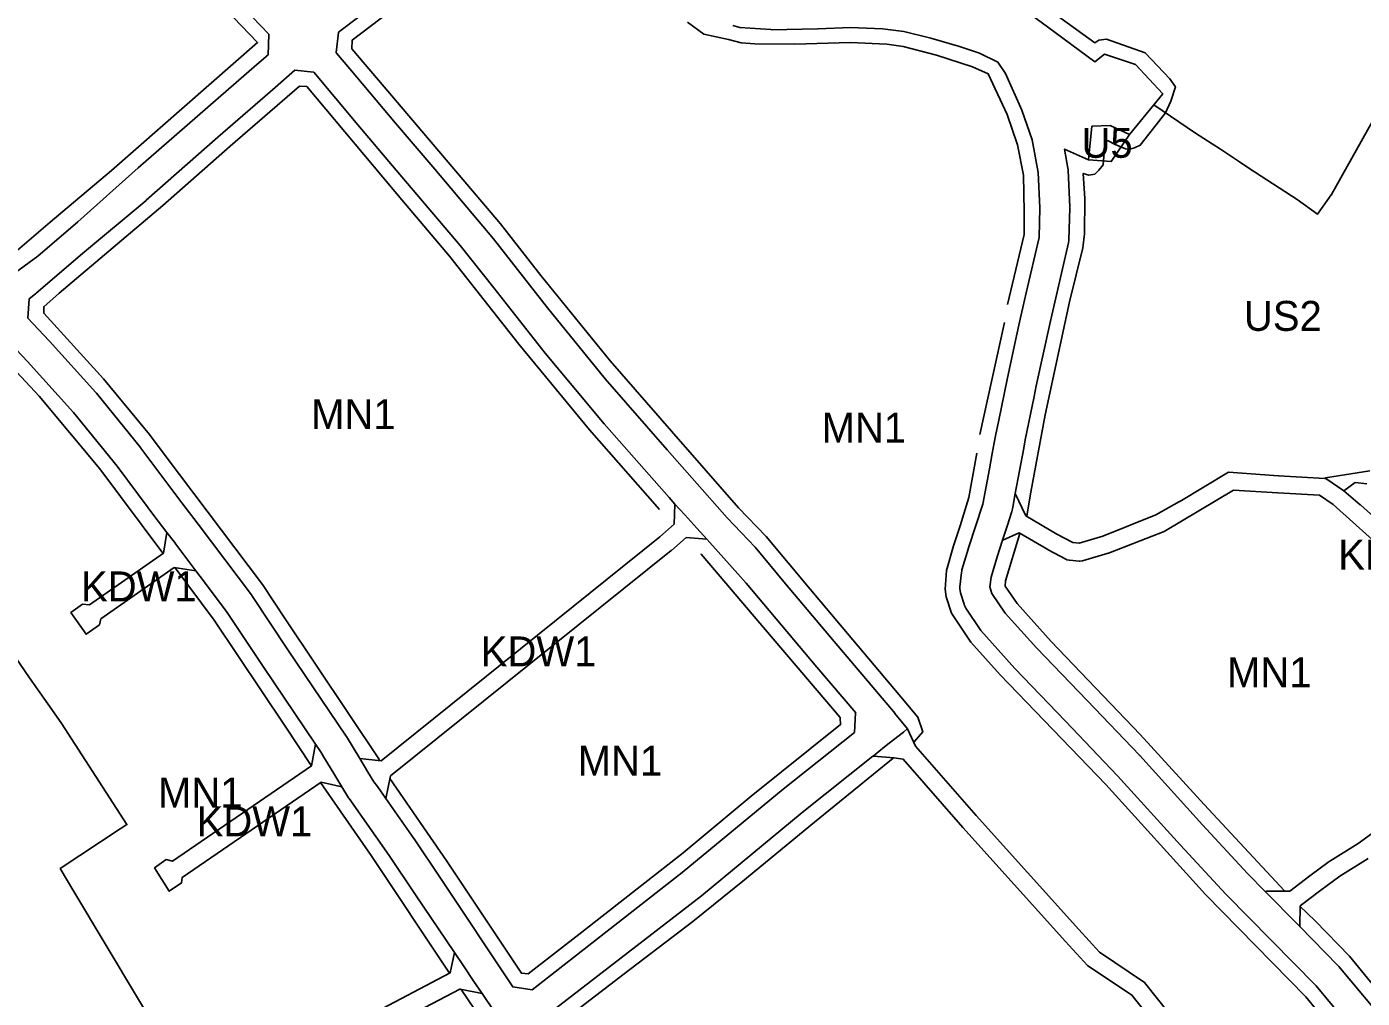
# Model space of a CAD drawing. Extents: x -284239 to -281592, y 34477 to 37267.
# Drawn here: x -283958.8 to -283512.6, y 34964.3 to 35288.9 of the extents above; entities that cross this region are included whole.
import ezdxf

# ---------------------------------------------------------------- set-up
doc = ezdxf.new("R2010")
doc.units = 0
for name, color, linetype in [('linie_rozgraniczajace', 7, 'Continuous'), ('linie_zabudowy_nieprzekraczalne', 7, 'Continuous'), ('oznaczenia_przeznaczen', 7, 'Continuous')]:
    doc.layers.add(name, color=color, linetype=linetype)

msp = doc.modelspace()

# ---------------------------------------------------------------- linework, layer by layer
at = {"layer": 'linie_rozgraniczajace'}
for points in [[(-283967.091, 35203.375), (-283955.019, 35212.204), (-283941.685, 35223.735), (-283921.504, 35241.754), (-283881.863, 35276.26), (-283878.079, 35279.504), (-283877.899, 35286.351), (-283897.359, 35306.712)], [(-283897.359, 35306.712), (-283877.899, 35286.351), (-283878.079, 35279.504), (-283881.863, 35276.26), (-283921.504, 35241.754), (-283941.685, 35223.735), (-283955.019, 35212.204), (-283967.091, 35203.375)], [(-283460.618, 35234.062), (-283475.613, 35245.965), (-283496.173, 35262.042), (-283502.975, 35267.607), (-283509.313, 35257.095), (-283522.917, 35232.825), (-283522.917, 35232.636), (-283523.014, 35232.725), (-283527.552, 35226.283), (-283534.386, 35231.101), (-283550.521, 35241.633), (-283553.587, 35243.683), (-283559.988, 35247.963), (-283568.279, 35253.341), (-283582.285, 35262.753), (-283579.201, 35266.417), (-283588.366, 35276.203), (-283598.698, 35279.683), (-283601.902, 35277.142), (-283617.703, 35288.854), (-283630.702, 35298.362), (-283632.444, 35304.207)], [(-283630.702, 35298.362), (-283617.703, 35288.854), (-283601.902, 35277.142), (-283598.698, 35279.683), (-283588.366, 35276.203), (-283579.201, 35266.417), (-283582.285, 35262.753), (-283590.352, 35252.893), (-283596.794, 35255.862), (-283602.913, 35255.619), (-283604.057, 35244.38), (-283612.117, 35247.946), (-283610.945, 35241.662), (-283610.891, 35241.076), (-283610.865, 35240.958), (-283610.339, 35228.584), (-283610.368, 35228.419), (-283610.336, 35228.247), (-283610.599, 35217.716), (-283610.626, 35217.587), (-283610.725, 35216.718), (-283616.314, 35192.455), (-283616.853, 35190.004), (-283621.5, 35168.889), (-283622.227, 35165.304), (-283625.17, 35150.802), (-283625.688, 35148.026), (-283628.518, 35132.864), (-283629.36, 35128.347), (-283629.705, 35126.763), (-283629.736, 35126.572), (-283631.126, 35122.327), (-283632.758, 35117.341), (-283634.585, 35111.762), (-283636.61, 35104.951), (-283636.972, 35101.693), (-283636.311, 35099.563), (-283631.912, 35092.964), (-283621.416, 35081.316), (-283604.552, 35063.795), (-283587.039, 35045.493), (-283586.996, 35045.426), (-283586.942, 35045.388), (-283565.967, 35022.178), (-283550.9, 35005.932), (-283545.059, 34999.989), (-283541.589, 34996.458), (-283537.347, 34992.143), (-283533.503, 34988.231), (-283520.736, 34975.24), (-283520.466, 34974.943), (-283507.888, 34959.86)], [(-283847.419, 35292.551), (-283854.627, 35287.038), (-283854.63, 35286.972), (-283855.381, 35280.213), (-283855.332, 35280.025), (-283850.849, 35274.762), (-283835.547, 35256.605), (-283822.414, 35241.303), (-283802.83, 35217.95), (-283784.844, 35194.939), (-283765.487, 35171.243), (-283744.761, 35147.547), (-283724.719, 35124.765), (-283715.412, 35115.002)], [(-283855.381, 35280.213), (-283854.63, 35286.972), (-283854.627, 35287.038), (-283847.419, 35292.551)], [(-283515.605, 34953.503), (-283528.014, 34968.381), (-283558.083, 34998.974), (-283558.183, 34999.078), (-283573.321, 35015.401), (-283594.314, 35038.631), (-283611.767, 35056.872), (-283628.678, 35074.44), (-283640.03, 35087.114), (-283645.032, 35094.617), (-283645.492, 35095.477), (-283645.647, 35095.909), (-283646.832, 35099.726), (-283647.057, 35101.208), (-283647.026, 35101.76), (-283646.5, 35106.499), (-283646.385, 35106.945), (-283646.323, 35107.372), (-283644.151, 35114.678), (-283644.11, 35114.809), (-283639.342, 35129.37), (-283637.136, 35141.192), (-283636.193, 35146.243), (-283635.518, 35149.861), (-283635.083, 35152.192), (-283634.031, 35157.385), (-283631.275, 35170.998), (-283628.396, 35184.082), (-283627.285, 35189.13), (-283626.62, 35192.153), (-283625.964, 35195.055), (-283624.833, 35199.979), (-283620.583, 35218.471), (-283620.337, 35228.328), (-283620.841, 35240.179), (-283622.876, 35251.095), (-283626.37, 35260.953), (-283631.776, 35273.273), (-283634.323, 35277.046), (-283640.479, 35280.018), (-283647.104, 35282.308), (-283656.773, 35285.016), (-283665.748, 35287.292), (-283672.885, 35288.153), (-283683.523, 35288.659), (-283694.343, 35288.144), (-283694.496, 35288.139), (-283710.03, 35287.876), (-283710.232, 35287.914), (-283720.495, 35288.596), (-283722.896, 35289.305)], [(-283722.896, 35289.305), (-283720.495, 35288.596), (-283710.232, 35287.914), (-283710.03, 35287.876), (-283694.496, 35288.139), (-283694.343, 35288.144), (-283683.523, 35288.659), (-283672.885, 35288.153), (-283665.748, 35287.292), (-283656.773, 35285.016), (-283647.104, 35282.308), (-283640.479, 35280.018), (-283634.323, 35277.046), (-283631.776, 35273.273), (-283626.37, 35260.953), (-283622.876, 35251.095), (-283620.841, 35240.179), (-283620.337, 35228.328), (-283620.583, 35218.471), (-283624.833, 35199.979), (-283625.964, 35195.055), (-283626.62, 35192.153), (-283627.285, 35189.13), (-283628.396, 35184.082), (-283631.275, 35170.998), (-283634.031, 35157.385), (-283635.083, 35152.192), (-283635.518, 35149.861), (-283636.193, 35146.243), (-283637.136, 35141.192), (-283639.342, 35129.37), (-283644.11, 35114.809), (-283644.151, 35114.678), (-283646.323, 35107.372), (-283646.385, 35106.945), (-283646.5, 35106.499), (-283647.026, 35101.76), (-283647.057, 35101.208), (-283646.832, 35099.726), (-283645.647, 35095.909), (-283645.492, 35095.477), (-283645.032, 35094.617), (-283640.03, 35087.114), (-283628.678, 35074.44), (-283611.767, 35056.872), (-283594.314, 35038.631), (-283573.321, 35015.401), (-283558.183, 34999.078), (-283558.083, 34998.974), (-283528.014, 34968.381), (-283515.605, 34953.503)], [(-283664.54, 35054.239), (-283664.589, 35054.271), (-283664.54, 35054.31), (-283668.767, 35059.383), (-283668.696, 35059.435), (-283688.976, 35083.426), (-283705.249, 35102.782), (-283715.412, 35115.002), (-283724.719, 35124.765), (-283744.761, 35147.547), (-283765.487, 35171.243), (-283784.844, 35194.939), (-283802.83, 35217.95), (-283822.414, 35241.303), (-283835.547, 35256.605), (-283850.849, 35274.762), (-283855.332, 35280.025), (-283855.381, 35280.213)], [(-283510.06, 35140.514), (-283524.877, 35138.133), (-283525.103, 35137.954), (-283540.523, 35138.846), (-283540.558, 35138.848), (-283545.143, 35139.113), (-283557.275, 35140.041), (-283573.548, 35130.294), (-283573.608, 35130.267), (-283573.684, 35130.232), (-283581.569, 35125.767), (-283599.272, 35118.677), (-283607.221, 35116.353), (-283609.339, 35116.523), (-283614.65, 35119.355), (-283624.971, 35125.499), (-283628.518, 35132.864), (-283625.688, 35148.026), (-283625.17, 35150.802), (-283622.227, 35165.304), (-283621.5, 35168.889), (-283616.853, 35190.004), (-283616.314, 35192.455), (-283610.725, 35216.718), (-283610.626, 35217.587), (-283610.599, 35217.716), (-283610.336, 35228.247), (-283610.368, 35228.419), (-283610.339, 35228.584), (-283610.865, 35240.958), (-283610.891, 35241.076), (-283610.945, 35241.662), (-283612.117, 35247.946), (-283604.057, 35244.38), (-283596.432, 35243.828), (-283590.352, 35252.893), (-283582.285, 35262.753), (-283568.279, 35253.341), (-283559.988, 35247.963), (-283553.587, 35243.683), (-283550.521, 35241.633), (-283534.386, 35231.101), (-283527.552, 35226.283), (-283523.014, 35232.725), (-283522.917, 35232.636), (-283522.917, 35232.825), (-283509.313, 35257.095)], [(-283782.296, 34929.748), (-283806.652, 34965.834), (-283809.348, 34969.828), (-283812.902, 34975.093), (-283815.901, 34979.537), (-283828.92, 34998.827), (-283837.64, 35011.988), (-283851.063, 35031.012), (-283851.15, 35031.168), (-283851.249, 35031.295), (-283853.451, 35034.911), (-283856.188, 35039.409), (-283859.469, 35044.8), (-283860.442, 35046.398), (-283862.32, 35049.187), (-283879.803, 35075.152), (-283891.789, 35093.211), (-283899.75, 35103.764), (-283902.28, 35107.118), (-283905.31, 35111.135), (-283908.957, 35115.969), (-283909.447, 35116.618), (-283911.957, 35119.889), (-283914.892, 35123.716), (-283914.924, 35123.757), (-283928.581, 35142.02), (-283943.14, 35160.014), (-283958.538, 35177.051), (-283965.895, 35184.8)], [(-283965.895, 35184.8), (-283958.538, 35177.051), (-283943.14, 35160.014), (-283928.581, 35142.02), (-283914.924, 35123.757), (-283914.892, 35123.716), (-283911.957, 35119.889), (-283913.126, 35113.031), (-283937.76, 35095.667), (-283940.141, 35095.932), (-283943.978, 35093.154), (-283938.951, 35085.877), (-283934.453, 35089.052), (-283934.056, 35091.037), (-283909.48, 35108.219), (-283902.28, 35107.118), (-283899.75, 35103.764), (-283891.789, 35093.211), (-283879.803, 35075.152), (-283862.32, 35049.187), (-283863.657, 35041.928), (-283910.111, 35010.074), (-283912.228, 35010.603), (-283916.064, 35007.825), (-283911.169, 35000.02), (-283907.068, 35002.798), (-283906.804, 35004.65), (-283860.408, 35036.511), (-283853.451, 35034.911), (-283851.249, 35031.295), (-283851.15, 35031.168), (-283851.063, 35031.012), (-283837.64, 35011.988), (-283828.92, 34998.827), (-283815.901, 34979.537), (-283817.35, 34972.75), (-283870.556, 34944.722)], [(-283503.756, 35112.492), (-283522.352, 35129.294), (-283526.942, 35132.354), (-283540.811, 35133.133), (-283555.628, 35134.002), (-283578.824, 35120.277), (-283597.369, 35112.988), (-283597.511, 35112.94), (-283606.067, 35110.439), (-283606.909, 35110.319), (-283607.148, 35110.328), (-283610.439, 35110.592), (-283611.348, 35110.81), (-283611.612, 35110.935), (-283617.536, 35114.094), (-283617.568, 35114.118), (-283617.658, 35114.164), (-283627.17, 35119.825), (-283632.708, 35117.32), (-283632.758, 35117.341), (-283631.126, 35122.327), (-283629.736, 35126.572), (-283629.705, 35126.763), (-283629.36, 35128.347), (-283628.518, 35132.864), (-283624.971, 35125.499), (-283614.65, 35119.355), (-283609.339, 35116.523), (-283607.221, 35116.353), (-283599.272, 35118.677), (-283581.569, 35125.767), (-283573.684, 35130.232), (-283573.608, 35130.267), (-283573.548, 35130.294), (-283557.275, 35140.041), (-283545.143, 35139.113), (-283540.558, 35138.848), (-283540.523, 35138.846), (-283525.103, 35137.954), (-283524.807, 35137.937), (-283518.767, 35133.76), (-283513.271, 35129.175), (-283513.241, 35129.148), (-283513.192, 35129.104), (-283499.654, 35116.872)], [(-283511.119, 35136.148), (-283514.969, 35136.607), (-283518.767, 35133.76), (-283524.807, 35137.937), (-283525.103, 35137.954), (-283524.877, 35138.133), (-283510.06, 35140.514)], [(-283499.654, 35116.872), (-283513.192, 35129.104), (-283513.241, 35129.148), (-283513.271, 35129.175), (-283518.767, 35133.76), (-283514.969, 35136.607), (-283511.119, 35136.148)], [(-283500.658, 35025.661), (-283513.918, 35016.002), (-283523.409, 35010.111), (-283523.513, 35010.028), (-283523.617, 35009.969), (-283530.072, 35005.169), (-283536.83, 35000.057), (-283544.648, 35000.057), (-283545.059, 34999.989), (-283550.9, 35005.932), (-283565.967, 35022.178), (-283586.942, 35045.388), (-283586.996, 35045.426), (-283587.039, 35045.493), (-283604.552, 35063.795), (-283621.416, 35081.316), (-283631.912, 35092.964), (-283636.311, 35099.563), (-283636.972, 35101.693), (-283636.61, 35104.951), (-283634.585, 35111.762), (-283632.758, 35117.341), (-283632.708, 35117.32), (-283627.17, 35119.825), (-283617.658, 35114.164), (-283617.568, 35114.118), (-283617.536, 35114.094), (-283611.612, 35110.935), (-283611.348, 35110.81), (-283610.439, 35110.592), (-283607.148, 35110.328), (-283606.909, 35110.319), (-283606.067, 35110.439), (-283597.511, 35112.94), (-283597.369, 35112.988), (-283578.824, 35120.277), (-283555.628, 35134.002), (-283540.811, 35133.133), (-283526.942, 35132.354), (-283522.352, 35129.294), (-283503.756, 35112.492)], [(-283715.412, 35115.002), (-283705.249, 35102.782), (-283688.976, 35083.426), (-283668.696, 35059.435), (-283668.767, 35059.383), (-283664.54, 35054.31), (-283664.589, 35054.271), (-283665.909, 35053.22), (-283670.607, 35049.479), (-283672.157, 35048.244), (-283675.981, 35045.199), (-283676.085, 35045.213), (-283699.758, 35026.36), (-283733.394, 34998.539), (-283784.602, 34959.014)], [(-283962.68, 35078.32), (-283957.788, 35071.359), (-283951.668, 35062.652), (-283947.21, 35056.31), (-283925.27, 35022.31), (-283927.512, 35020.829), (-283947.54, 35007.6), (-283943, 35000), (-283911.001, 34946.396)], [(-283911.001, 34946.396), (-283943, 35000), (-283947.54, 35007.6), (-283927.512, 35020.829), (-283925.27, 35022.31), (-283947.21, 35056.31), (-283951.668, 35062.652), (-283957.788, 35071.359), (-283962.68, 35078.32)], [(-283580.307, 34953.784), (-283589.568, 34965.359), (-283604.367, 34975.171), (-283611.735, 34983.25), (-283646.006, 35021.357), (-283646.026, 35021.382), (-283665.933, 35044.135), (-283669.037, 35044.646), (-283668.984, 35044.585), (-283675.981, 35045.199), (-283672.157, 35048.244), (-283670.607, 35049.479), (-283665.909, 35053.22), (-283664.589, 35054.271), (-283664.54, 35054.239), (-283661.893, 35048.5), (-283641.531, 35025.353), (-283607.288, 34987.276), (-283600.406, 34979.732), (-283585.334, 34969.593), (-283552.394, 34928.119)], [(-283552.394, 34928.119), (-283585.334, 34969.593), (-283600.406, 34979.732), (-283607.288, 34987.276), (-283641.531, 35025.353), (-283661.893, 35048.5), (-283664.54, 35054.239)], [(-283784.602, 34959.014), (-283733.394, 34998.539), (-283699.758, 35026.36), (-283676.085, 35045.213), (-283675.981, 35045.199), (-283668.984, 35044.585), (-283669.037, 35044.646), (-283665.933, 35044.135), (-283646.026, 35021.382), (-283646.006, 35021.357), (-283611.735, 34983.25), (-283604.367, 34975.171), (-283589.568, 34965.359), (-283580.307, 34953.784)], [(-283510.66, 35010.962), (-283520.138, 35005.08), (-283526.471, 35000.37), (-283533.39, 34995.137), (-283533.503, 34988.231), (-283537.347, 34992.143), (-283541.589, 34996.458), (-283545.059, 34999.989), (-283544.648, 35000.057), (-283536.83, 35000.057), (-283530.072, 35005.169), (-283523.617, 35009.969), (-283523.513, 35010.028), (-283523.409, 35010.111), (-283513.918, 35016.002), (-283500.658, 35025.661)], [(-283507.888, 34959.86), (-283520.466, 34974.943), (-283520.736, 34975.24), (-283533.503, 34988.231), (-283533.39, 34995.137), (-283526.471, 35000.37), (-283520.138, 35005.08), (-283510.66, 35010.962)], [(-283867.645, 34939.298), (-283814.052, 34967.365), (-283813.935, 34967.344), (-283806.652, 34965.834), (-283782.296, 34929.748)]]:
    msp.add_lwpolyline(points, dxfattribs=at)
for points in [[(-283958.419, 35191.541), (-283951.244, 35183.891), (-283951.206, 35183.834), (-283951.16, 35183.802), (-283935.629, 35166.618), (-283935.607, 35166.583), (-283935.452, 35166.41), (-283920.747, 35148.236), (-283920.718, 35148.187), (-283920.629, 35148.085), (-283906.934, 35129.77), (-283901.497, 35122.684), (-283901.476, 35122.657), (-283883.714, 35099.113), (-283883.651, 35099.003), (-283883.54, 35098.866), (-283871.488, 35080.706), (-283852.083, 35051.888), (-283852.023, 35051.775), (-283851.96, 35051.695), (-283847.505, 35044.377), (-283844.875, 35040.056), (-283842.795, 35036.639), (-283841.633, 35034.992), (-283838.806, 35030.985), (-283829.427, 35017.694), (-283829.393, 35017.633), (-283829.344, 35017.573), (-283820.59, 35004.359), (-283796.401, 34968.072), (-283789.937, 34967.093), (-283789.907, 34967.075), (-283739.761, 35006.25), (-283706.086, 35034.101), (-283706.026, 35034.152), (-283682.25, 35053.075), (-283681.844, 35059.633), (-283681.786, 35059.652), (-283694.857, 35074.919), (-283718.438, 35102.954), (-283730.6, 35116.6), (-283731.577, 35117.654), (-283734.894, 35121.327), (-283738.929, 35125.769), (-283742.215, 35129.386), (-283744.19, 35131.56), (-283765.83, 35156.169), (-283785.529, 35179.751), (-283802.716, 35201.62), (-283813.964, 35215.723), (-283835.376, 35240.903), (-283848.109, 35256.034), (-283862.904, 35273.647), (-283862.984, 35273.642), (-283869.188, 35274.377), (-283875.737, 35268.568), (-283875.772, 35268.547), (-283875.79, 35268.523), (-283894.949, 35252.006), (-283918.815, 35230.919), (-283918.917, 35230.829), (-283940.181, 35213.131), (-283955.625, 35199.799), (-283955.669, 35199.772), (-283955.812, 35199.646), (-283957.932, 35197.997)], [(-283958.419, 35191.541), (-283957.932, 35197.997), (-283955.812, 35199.646), (-283955.669, 35199.772), (-283955.625, 35199.799), (-283940.181, 35213.131), (-283918.917, 35230.829), (-283918.815, 35230.919), (-283894.949, 35252.006), (-283875.79, 35268.523), (-283875.772, 35268.547), (-283875.737, 35268.568), (-283869.188, 35274.377), (-283862.984, 35273.642), (-283862.904, 35273.647), (-283848.109, 35256.034), (-283835.376, 35240.903), (-283813.964, 35215.723), (-283802.716, 35201.62), (-283785.529, 35179.751), (-283765.83, 35156.169), (-283744.19, 35131.56), (-283742.215, 35129.386), (-283742.244, 35129.378), (-283742.484, 35122.643), (-283747.241, 35118.461), (-283840.407, 35043.63), (-283847.505, 35044.377), (-283851.96, 35051.695), (-283852.023, 35051.775), (-283852.083, 35051.888), (-283871.488, 35080.706), (-283883.54, 35098.866), (-283883.651, 35099.003), (-283883.714, 35099.113), (-283901.476, 35122.657), (-283901.497, 35122.684), (-283906.934, 35129.77), (-283920.629, 35148.085), (-283920.718, 35148.187), (-283920.747, 35148.236), (-283935.452, 35166.41), (-283935.607, 35166.583), (-283935.629, 35166.618), (-283951.16, 35183.802), (-283951.206, 35183.834), (-283951.244, 35183.891)], [(-283604.057, 35244.38), (-283602.913, 35255.619), (-283596.794, 35255.862), (-283590.352, 35252.893), (-283596.432, 35243.828)], [(-283847.505, 35044.377), (-283840.407, 35043.63), (-283747.241, 35118.461), (-283742.484, 35122.643), (-283742.244, 35129.378), (-283742.215, 35129.386), (-283738.929, 35125.769), (-283734.894, 35121.327), (-283731.577, 35117.654), (-283738.459, 35118.193), (-283743.339, 35113.906), (-283743.428, 35113.828), (-283837.216, 35038.537), (-283838.806, 35030.985), (-283841.633, 35034.992), (-283842.795, 35036.639), (-283844.875, 35040.056)], [(-283943.978, 35093.154), (-283940.141, 35095.932), (-283937.76, 35095.667), (-283913.126, 35113.031), (-283911.957, 35119.889), (-283909.447, 35116.618), (-283908.957, 35115.969), (-283905.31, 35111.135), (-283902.28, 35107.118), (-283909.48, 35108.219), (-283934.056, 35091.037), (-283934.453, 35089.052), (-283938.951, 35085.877)], [(-283838.806, 35030.985), (-283837.216, 35038.537), (-283743.428, 35113.828), (-283743.339, 35113.906), (-283738.459, 35118.193), (-283731.577, 35117.654), (-283730.6, 35116.6), (-283718.438, 35102.954), (-283694.857, 35074.919), (-283681.786, 35059.652), (-283681.844, 35059.633), (-283682.25, 35053.075), (-283706.026, 35034.152), (-283706.086, 35034.101), (-283739.761, 35006.25), (-283789.907, 34967.075), (-283789.937, 34967.093), (-283796.401, 34968.072), (-283820.59, 35004.359), (-283829.344, 35017.573), (-283829.393, 35017.633), (-283829.427, 35017.694)], [(-283916.064, 35007.825), (-283912.228, 35010.603), (-283910.111, 35010.074), (-283863.657, 35041.928), (-283862.32, 35049.187), (-283860.442, 35046.398), (-283859.469, 35044.8), (-283856.188, 35039.409), (-283853.451, 35034.911), (-283860.408, 35036.511), (-283906.804, 35004.65), (-283907.068, 35002.798), (-283911.169, 35000.02)], [(-283876.244, 34943.267), (-283872.54, 34945.251), (-283870.556, 34944.722), (-283817.35, 34972.75), (-283815.901, 34979.537), (-283812.902, 34975.093), (-283809.348, 34969.828), (-283806.652, 34965.834), (-283813.935, 34967.344), (-283814.052, 34967.365), (-283867.645, 34939.298), (-283868.042, 34937.578), (-283871.879, 34935.726)]]:
    msp.add_lwpolyline(points, close=True, dxfattribs=at)
at = {"layer": 'linie_zabudowy_nieprzekraczalne'}
for points in [[(-283505.4, 35472.008), (-283529.874, 35442.44), (-283544.029, 35426.433), (-283573.398, 35394.352), (-283590.199, 35379.006), (-283593.374, 35375.435), (-283596.946, 35371.4), (-283602.767, 35361.478), (-283614.541, 35335.482), (-283627.505, 35308.759), (-283627.505, 35305.055), (-283626.447, 35301.351), (-283601.973, 35283.492), (-283600.65, 35284.418), (-283598.004, 35284.748), (-283585.172, 35280.118), (-283576.839, 35271.442), (-283574.995, 35268.777), (-283576.583, 35264.015), (-283578.302, 35260.046)], [(-283990.921, 35187.021), (-283984.165, 35194.724), (-283971.994, 35205.969), (-283966.57, 35210.202), (-283950.959, 35223.563), (-283930.454, 35240.828), (-283881.638, 35283.624), (-283935.094, 35339.421)], [(-283827.928, 35301.351), (-283850.02, 35284.418), (-283850.153, 35281.507), (-283831.103, 35259.084), (-283800.543, 35222.968), (-283787.05, 35205.704), (-283763.898, 35177.261), (-283743.393, 35153.779), (-283721.036, 35128.115), (-283711.775, 35118.59), (-283697.091, 35100.929), (-283666.796, 35064.945), (-283661.117, 35058.169), (-283659.397, 35053.274), (-283662.308, 35049.966)], [(-283724.353, 35284.652), (-283732.555, 35286.372), (-283737.979, 35290.341)], [(-283631.087, 35196.017), (-283625.521, 35219.396), (-283625.521, 35227.069), (-283625.786, 35239.306), (-283627.77, 35249.36), (-283631.21, 35259.547), (-283637.56, 35273.173), (-283642.851, 35275.488), (-283654.89, 35279.324), (-283666.002, 35282.235), (-283671.426, 35283.029), (-283683.597, 35283.558), (-283702.25, 35283.029), (-283715.49, 35283.148), (-283720.119, 35283.462), (-283724.353, 35284.652)], [(-283747.378, 35127.537), (-283754.638, 35135.788), (-283770.778, 35154.176), (-283794.326, 35182.817), (-283817.477, 35212.186), (-283833.484, 35231.038), (-283865.234, 35268.873), (-283867.615, 35269.006), (-283890.766, 35248.963), (-283913.256, 35229.12), (-283947.917, 35199.883), (-283953.076, 35195.319), (-283953.076, 35193.202), (-283933.1, 35171.242), (-283917.754, 35152.589), (-283912.198, 35145.114), (-283880.051, 35102.516), (-283872.378, 35091.073), (-283840.902, 35043.881)], [(-283578.302, 35260.046), (-283581.468, 35256.041), (-283586.76, 35249.294), (-283588.744, 35248.368), (-283590.199, 35247.971), (-283591.654, 35248.104), (-283595.094, 35249.559), (-283597.475, 35250.749), (-283598.534, 35250.882), (-283599.195, 35242.746), (-283600.65, 35240.894), (-283601.973, 35239.571), (-283603.957, 35239.306), (-283605.81, 35239.835), (-283605.28, 35231.501), (-283605.413, 35219.727), (-283605.942, 35214.964), (-283610.44, 35196.907), (-283618.51, 35159.203), (-283623.272, 35133.406), (-283624.605, 35125.505)], [(-283640.347, 35152.625), (-283632.145, 35190.064)], [(-283913.266, 35112.937), (-283934.29, 35141.146), (-283954.663, 35165.487), (-283968.289, 35180.039), (-283970.538, 35179.775), (-283978.741, 35171.44), (-283994.219, 35154.242), (-284002.641, 35145.469)], [(-283497.34, 34853.513), (-283474.973, 34876.892), (-283473.915, 34886.021), (-283475.502, 34889.394), (-283484.762, 34906.195), (-283495.214, 34920.615), (-283510.824, 34939.599), (-283531.462, 34964.734), (-283553.819, 34987.555), (-283564.931, 34998.932), (-283598.269, 35035.643), (-283633.591, 35072.288), (-283643.38, 35083.202), (-283649.863, 35092.991), (-283651.583, 35098.415), (-283651.979, 35100.929), (-283651.45, 35107.147), (-283649.201, 35115.481), (-283646.952, 35122.095), (-283644.042, 35131.554), (-283641.406, 35146.407)], [(-283626.986, 35119.552), (-283631.739, 35103.773), (-283631.871, 35101.987), (-283627.902, 35096.166), (-283616.525, 35083.466), (-283586.76, 35052.444), (-283565.461, 35029.028), (-283538.615, 35000.225)], [(-283686.905, 35055.685), (-283687.037, 35058.066), (-283711.908, 35087.369), (-283733.471, 35112.637), (-283733.576, 35112.645)], [(-283863.788, 35042.029), (-283872.378, 35055.222), (-283896.19, 35090.544), (-283909.165, 35108.043)], [(-283837.462, 35037.663), (-283818.403, 35010.11), (-283793.532, 34972.672), (-283791.283, 34972.407), (-283773.291, 34986.364), (-283739.424, 35012.889), (-283716.803, 35031.806), (-283686.905, 35055.751)], [(-283669.319, 35044.542), (-283695.636, 35023.075), (-283719.581, 35003.363), (-283736.249, 34989.936), (-283759.136, 34972.473), (-283779.773, 34956.598), (-283780.303, 34953.159), (-283774.085, 34943.501), (-283766.025, 34932.756)], [(-283533.455, 34995.065), (-283528.287, 34990.2), (-283516.909, 34978.36), (-283488.731, 34943.964), (-283480, 34933.712), (-283467.829, 34916.646), (-283457.378, 34897.596), (-283456.055, 34897.332), (-283430.655, 34923.988), (-283413.06, 34942.112), (-283404.461, 34950.248), (-283379.326, 34974.325), (-283373.108, 34979.419), (-283348.105, 35000.321), (-283336.596, 35009.317), (-283315.164, 35025.721), (-283306.433, 35031.806), (-283291.494, 35041.235)], [(-283817.486, 34972.708), (-283843.67, 35012.029), (-283860.613, 35036.34)], [(-283787.711, 34928.949), (-283813.65, 34967.152)]]:
    msp.add_lwpolyline(points, dxfattribs=at)

# ---------------------------------------------------------------- texts
at = {"layer": 'oznaczenia_przeznaczen'}
for s, p in [('U5', (-283606.405, 35245.079)), ('US2', (-283552.135, 35187.258)), ('MN1', (-283863.755, 35154.424)), ('MN1', (-283693.234, 35149.917)), ('KDW1', (-283520.641, 35107.492)), ('KDW1', (-283940.619, 35096.892)), ('KDW1', (-283807.074, 35075.166)), ('MN1', (-283557.779, 35068.205)), ('MN1', (-283774.703, 35038.642)), ('MN1', (-283914.917, 35028.007)), ('KDW1', (-283901.994, 35018.397))]:
    msp.add_text(s, height=10, dxfattribs=at).set_placement(p)

doc.saveas('drawing.dxf')
